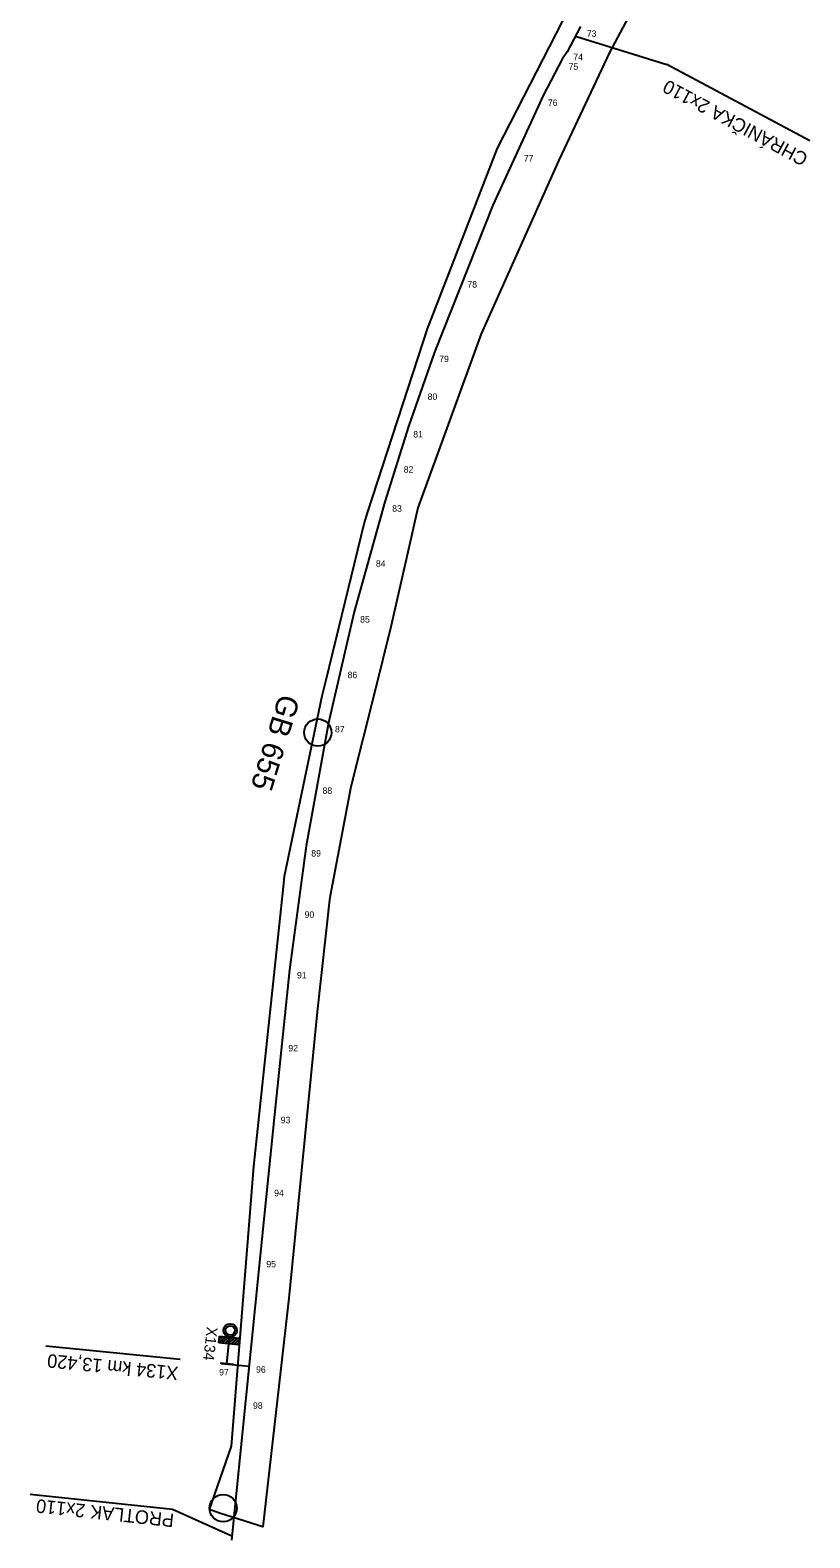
# Model space of a CAD drawing. Extents: x -743546 to -74, y -1128126 to -103.
# Drawn here: x -743366.8 to -743222.4, y -1127521 to -1127241.8 of the extents above; entities that cross this region are included whole.
import ezdxf

# ---------------------------------------------------------------- set-up
doc = ezdxf.new("R2010")
doc.units = 0
for name, color, linetype in [('_Zabezpečovací zařízení', 7, 'Continuous'), ('_Zabezpečovací zařízení_trasa', 7, 'Continuous'), ('křížky', 7, 'Continuous'), ('Nový stav', 7, 'Continuous'), ('Vrstva 53', 7, 'Continuous'), ('Vrstva 60', 7, 'Continuous'), ('ŽBP', 7, 'Continuous')]:
    doc.layers.add(name, color=color, linetype=linetype)

# ---------------------------------------------------------------- blocks, each defined once
blk = doc.blocks.new('POINT_DISPLAY')
blk.add_line((0, 0), (0, 0))

msp = doc.modelspace()

# ---------------------------------------------------------------- linework, layer by layer
at = {"layer": '_Zabezpečovací zařízení'}
for p, q in [((-743331.88, -1127484.91), (-743331.75, -1127483.67)), ((-743331.88, -1127484.9), (-743330.52, -1127483.8)), ((-743328.15, -1127485.3), (-743331.88, -1127484.91)), ((-743331.82, -1127484.34), (-743331.08, -1127483.74)), ((-743331.76, -1127483.78), (-743331.64, -1127483.68)), ((-743331.75, -1127483.67), (-743328.02, -1127484.05)), ((-743331.34, -1127484.97), (-743329.96, -1127483.85)), ((-743330.78, -1127485.03), (-743329.94, -1127484.34)), ((-743330.4, -1127488.84), (-743329.89, -1127483.86)), ((-743330.22, -1127485.08), (-743330, -1127484.9)), ((-743330, -1127484.9), (-743328.85, -1127483.97)), ((-743329.94, -1127484.34), (-743329.41, -1127483.91)), ((-743329.66, -1127485.14), (-743328.29, -1127484.03)), ((-743329.1, -1127485.2), (-743328.05, -1127484.35)), ((-743328.54, -1127485.26), (-743328.11, -1127484.91)), ((-743328.02, -1127484.05), (-743328.15, -1127485.3)), ((-743329.16, -1127488.96), (-743331.64, -1127488.71))]:
    msp.add_line(p, q, dxfattribs=at)
for radius in [1.25, 0.875]:
    msp.add_circle((-743329.76, -1127482.62), radius, dxfattribs=at)
at = {"layer": '_Zabezpečovací zařízení_trasa'}
for points in [[(-743264.86, -1127241.11), (-743267.34, -1127245.82), (-743268.29, -1127247.16), (-743271.71, -1127253.75), (-743281.12, -1127274.2), (-743291.92, -1127301.42), (-743296.72, -1127315.22), (-743301.12, -1127329.13), (-743306.79, -1127349.51), (-743311.54, -1127370.06), (-743315.69, -1127392.87), (-743318.79, -1127415.84), (-743321.57, -1127442.6), (-743324.27, -1127469.35), (-743329.51, -1127521.46)], [(-743331.4, -1127488.73), (-743326.22, -1127489.25)]]:
    msp.add_lwpolyline(points, dxfattribs=at)
at = {"layer": 'Nový stav'}
for p, q in [((-743265.82, -1127242.93), (-743248.86, -1127248.15)), ((-743222.38, -1127262.3), (-743248.86, -1127248.15)), ((-743339.05, -1127488), (-743363.93, -1127485.56)), ((-743339.05, -1127488), (-743363.93, -1127485.56)), ((-743340.45, -1127515.81), (-743366.81, -1127512.98)), ((-743340.45, -1127515.81), (-743366.81, -1127512.98)), ((-743329.44, -1127520.71), (-743340.45, -1127515.81)), ((-743329.44, -1127520.71), (-743340.45, -1127515.81))]:
    msp.add_line(p, q, dxfattribs=at)
at = {"layer": 'Vrstva 53'}
msp.add_lwpolyline([(-743245.75, -1127220.06), (-743259.48, -1127245.93), (-743268.91, -1127265.85), (-743283.26, -1127298.02), (-743294.99, -1127330.28), (-743295.73, -1127333.53), (-743296.23, -1127335.74), (-743299.98, -1127352.31), (-743302.98, -1127364.26), (-743307.41, -1127381.95), (-743311.22, -1127402.11), (-743311.36, -1127402.88), (-743313.62, -1127423.64), (-743318.91, -1127476.67), (-743323.69, -1127519.01), (-743331.74, -1127516.48), (-743333.57, -1127515.78), (-743329.5, -1127504.03), (-743325.36, -1127452.28), (-743319.91, -1127400.47), (-743319.7, -1127398.48), (-743312.73, -1127365.1), (-743312.01, -1127362.15), (-743304.91, -1127333.26), (-743304.3, -1127331.19), (-743293.07, -1127296.72), (-743292.92, -1127296.34), (-743280.26, -1127263.68), (-743264.54, -1127233.06)], dxfattribs=at)
at = {"layer": 'Vrstva 60'}
for p, q in [((-743268.29, -1127247.16), (-743268.29, -1127247.16)), ((-743267.34, -1127245.82), (-743267.34, -1127245.82)), ((-743271.71, -1127253.75), (-743271.71, -1127253.75)), ((-743276.42, -1127263.97), (-743276.42, -1127263.97)), ((-743286.52, -1127287.81), (-743286.52, -1127287.81)), ((-743291.92, -1127301.42), (-743291.92, -1127301.42)), ((-743294.32, -1127308.32), (-743294.32, -1127308.32)), ((-743296.72, -1127315.22), (-743296.72, -1127315.22)), ((-743298.92, -1127322.18), (-743298.92, -1127322.18)), ((-743301.12, -1127329.13), (-743301.12, -1127329.13)), ((-743303.95, -1127339.32), (-743303.95, -1127339.32)), ((-743306.79, -1127349.51), (-743306.79, -1127349.51)), ((-743309.16, -1127359.78), (-743309.16, -1127359.78)), ((-743311.54, -1127370.06), (-743311.54, -1127370.06)), ((-743313.61, -1127381.46), (-743313.61, -1127381.46)), ((-743315.69, -1127392.87), (-743315.69, -1127392.87)), ((-743317.24, -1127404.35), (-743317.24, -1127404.35)), ((-743318.79, -1127415.84), (-743318.79, -1127415.84)), ((-743320.18, -1127429.22), (-743320.18, -1127429.22)), ((-743321.57, -1127442.6), (-743321.57, -1127442.6)), ((-743322.92, -1127455.97), (-743322.92, -1127455.97)), ((-743324.27, -1127469.35), (-743324.27, -1127469.35)), ((-743330.4, -1127488.84), (-743330.4, -1127488.84)), ((-743326.22, -1127489.25), (-743326.22, -1127489.25)), ((-743326.89, -1127495.41), (-743326.89, -1127495.41))]:
    msp.add_line(p, q, dxfattribs=at)
at = {"layer": 'ŽBP'}
for centre in [(-743313.54, -1127371.89), (-743331.07, -1127515.54)]:
    msp.add_circle(centre, 2.52, dxfattribs=at)

# ---------------------------------------------------------------- block references
at = {"layer": 'křížky', "xscale": 10, "yscale": 10, "rotation": 61.14491455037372}
for p in [(-743268.29, -1127247.16), (-743267.34, -1127245.82), (-743271.71, -1127253.75), (-743276.42, -1127263.97), (-743286.52, -1127287.81), (-743291.92, -1127301.42), (-743294.32, -1127308.32), (-743296.72, -1127315.22), (-743298.92, -1127322.18), (-743301.12, -1127329.13), (-743303.95, -1127339.32), (-743306.79, -1127349.51), (-743309.16, -1127359.78), (-743311.54, -1127370.06), (-743313.61, -1127381.46), (-743315.69, -1127392.87), (-743317.24, -1127404.35), (-743318.79, -1127415.84), (-743320.18, -1127429.22), (-743321.57, -1127442.6), (-743322.92, -1127455.97), (-743324.27, -1127469.35), (-743330.4, -1127488.84), (-743326.22, -1127489.25), (-743326.89, -1127495.41)]:
    msp.add_blockref('POINT_DISPLAY', p, dxfattribs=at)

# ---------------------------------------------------------------- texts
at = {"layer": '_Zabezpečovací zařízení'}
msp.add_text('X134', height=2, rotation=263.5157, dxfattribs=at).set_placement((-743334.07, -1127481.88))
at = {"layer": 'Nový stav'}
for s, rotation, p in [('CHRÁNIČKA 2x110', 151.8668, (-743222.5, -1127264.9)), ('X134 km 13,420', 174.395, (-743339.28, -1127489.34)), ('X134 km 13,420', 174.395, (-743339.28, -1127489.34)), ('PROTLAK 2x110', 173.8668, (-743340.06, -1127516.59)), ('PROTLAK 2x110', 173.8668, (-743340.06, -1127516.59))]:
    msp.add_text(s, height=2.5, rotation=rotation, dxfattribs=at).set_placement(p)
at = {"layer": 'Vrstva 60'}
for s, p in [('73', (-743263.7, -1127243.04)), ('75', (-743267.07, -1127249.15)), ('74', (-743266.2, -1127247.36)), ('76', (-743270.91, -1127255.84)), ('77', (-743275.37, -1127266.13)), ('78', (-743285.82, -1127289.47)), ('79', (-743291.04, -1127303.28)), ('80', (-743293.18, -1127310.29)), ('81', (-743295.85, -1127317.24)), ('82', (-743297.61, -1127323.76)), ('83', (-743299.75, -1127330.98)), ('84', (-743302.76, -1127341.18)), ('85', (-743305.69, -1127351.52)), ('86', (-743308.01, -1127361.82)), ('87', (-743310.34, -1127371.86)), ('88', (-743312.65, -1127383.24)), ('89', (-743314.74, -1127394.85)), ('90', (-743315.97, -1127406.21)), ('91', (-743317.39, -1127417.42)), ('92', (-743318.99, -1127430.95)), ('93', (-743320.41, -1127444.25)), ('94', (-743321.61, -1127457.77)), ('95', (-743323.07, -1127470.94)), ('97', (-743331.81, -1127490.96)), ('96', (-743324.96, -1127490.45)), ('98', (-743325.53, -1127497.14))]:
    msp.add_text(s, height=1.2, dxfattribs=at).set_placement(p)
at = {"layer": 'ŽBP'}
msp.add_text('GB 655', height=4, rotation=252.7006, dxfattribs=at).set_placement((-743320.6, -1127364.55))

doc.saveas('drawing.dxf')
